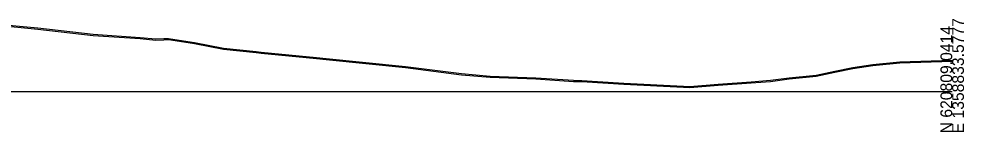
# Model space of a CAD drawing. Extents: x -26 to 803, y -27 to 3586.
# Drawn here: x 577.3 to 802.8, y 990.3 to 1017.3 of the extents above; entities that cross this region are included whole.
import ezdxf

# ---------------------------------------------------------------- set-up
doc = ezdxf.new("R2010")
doc.units = 0
for name, color, linetype in [('DESIGN - SHEET - Light Grid', 7, 'Continuous'), ('SURVEY - GROUND - Bottom of Topsoil Layer', 7, 'Continuous'), ('SURVEY - GROUND - Top of Ground', 7, 'Continuous')]:
    doc.layers.add(name, color=color, linetype=linetype)

msp = doc.modelspace()

# ---------------------------------------------------------------- linework, layer by layer
at = {"layer": 'DESIGN - SHEET - Light Grid'}
msp.add_line((400, 1000), (800, 1000), dxfattribs=at)
at = {"layer": 'SURVEY - GROUND - Bottom of Topsoil Layer'}
for p, q in [((560.97, 1016.83), (581.85, 1014.89)), ((581.85, 1014.89), (595.05, 1013.37)), ((595.05, 1013.37), (606.26, 1012.64)), ((606.26, 1012.64), (609.99, 1012.26)), ((609.99, 1012.26), (611.92, 1012.34)), ((611.92, 1012.34), (613.06, 1012.35)), ((613.06, 1012.35), (619.2, 1011.45)), ((619.2, 1011.45), (626.14, 1010.07)), ((626.14, 1010.07), (633.91, 1009.31)), ((633.91, 1009.31), (635.13, 1009.12)), ((635.13, 1009.12), (648.31, 1007.83)), ((648.31, 1007.83), (650.63, 1007.58)), ((650.63, 1007.58), (669.59, 1005.71)), ((776.3, 1005.49), (781.05, 1006.21)), ((781.05, 1006.21), (787.49, 1006.79)), ((787.49, 1006.79), (800, 1007.22)), ((669.59, 1005.71), (682.91, 1004)), ((682.91, 1004), (689.8, 1003.41)), ((761.11, 1003.01), (767.51, 1003.67)), ((767.51, 1003.67), (771.97, 1004.62)), ((771.97, 1004.62), (776.3, 1005.49)), ((689.8, 1003.41), (700.68, 1002.97)), ((700.68, 1002.97), (709.66, 1002.41)), ((709.66, 1002.41), (711.66, 1002.37)), ((711.66, 1002.37), (721.67, 1001.74)), ((721.67, 1001.74), (735.9, 1001.02)), ((737.41, 1000.94), (744.2, 1001.5)), ((744.2, 1001.5), (752.06, 1002.06)), ((752.06, 1002.06), (756.68, 1002.4)), ((756.68, 1002.4), (761.11, 1003.01)), ((735.9, 1001.02), (737.41, 1000.94))]:
    msp.add_line(p, q, dxfattribs=at)
at = {"layer": 'SURVEY - GROUND - Top of Ground'}
msp.add_lwpolyline([(560.97, 1017.08), (581.85, 1015.14), (595.05, 1013.62), (606.26, 1012.89), (609.99, 1012.51), (611.92, 1012.59), (613.06, 1012.6), (619.2, 1011.7), (626.14, 1010.32), (633.91, 1009.56), (635.13, 1009.37), (648.31, 1008.08), (650.63, 1007.83), (669.59, 1005.96), (682.91, 1004.25), (689.8, 1003.66), (700.68, 1003.22), (709.66, 1002.66), (711.66, 1002.62), (721.67, 1001.99), (735.9, 1001.27), (737.41, 1001.19), (744.2, 1001.75), (752.06, 1002.31), (756.68, 1002.65), (761.11, 1003.26), (767.51, 1003.92), (771.97, 1004.87), (776.3, 1005.74), (781.05, 1006.46), (787.49, 1007.04), (800, 1007.47)], dxfattribs=at)

# ---------------------------------------------------------------- texts
at = {"layer": 'DESIGN - SHEET - Light Grid'}
for s, p in [('E 1358833.5777', (802.8, 990)), ('N 620809.0414', (800, 990))]:
    msp.add_text(s, height=2.8, rotation=90, dxfattribs=at).set_placement(p)

doc.saveas('drawing.dxf')
